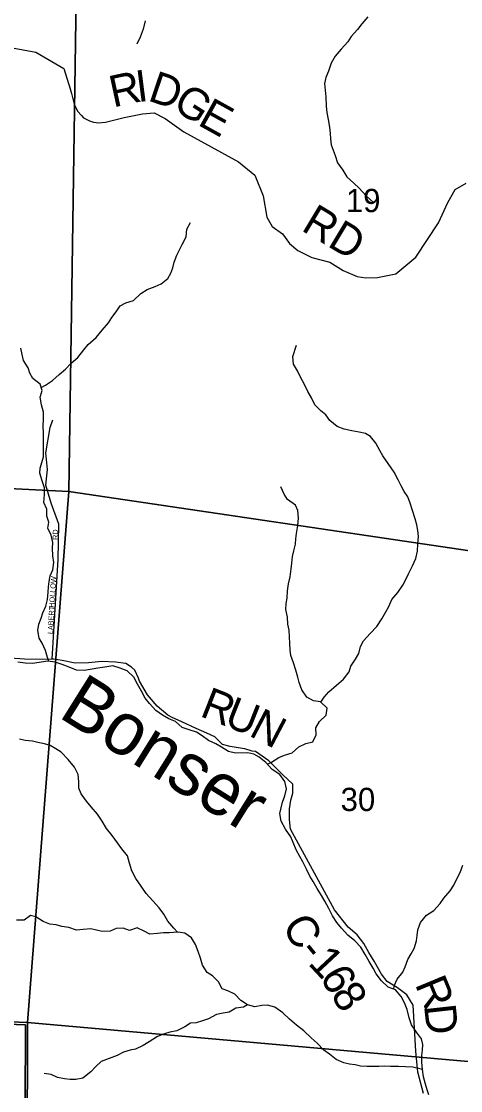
# Model space of a CAD drawing. Extents: x 1624196 to 2029251, y 146837 to 440034.
# Drawn here: x 1851645 to 1855817, y 286524 to 296690 of the extents above; entities that cross this region are included whole.
import ezdxf

# ---------------------------------------------------------------- set-up
doc = ezdxf.new("R2010")
doc.units = 0
for name, color, linetype in [('GM_X_County_Road', 7, 'Continuous'), ('GM_X_County_Road_Text', 7, 'Continuous'), ('GM_X_Minor_River', 7, 'Continuous'), ('GM_X_Minor_River_Text', 7, 'Continuous'), ('GM_X_Section', 7, 'Continuous'), ('GM_X_Section_Text', 7, 'Continuous'), ('GM_X_Township', 7, 'Continuous'), ('GM_X_Township_Subdivision', 7, 'Continuous'), ('GM_X_Township_Subdivision_Text', 7, 'Continuous')]:
    doc.layers.add(name, color=color, linetype=linetype)

msp = doc.modelspace()

# ---------------------------------------------------------------- linework, layer by layer
at = {"layer": 'GM_X_County_Road'}
for points in [[(1851418, 296464), (1851781, 296398), (1852048, 296243), (1852109, 296047), (1852120, 296004), (1852147, 295901), (1852176, 295837), (1852214, 295795), (1852233, 295772), (1852292, 295745), (1852331, 295732), (1852379, 295724), (1852445, 295730), (1852621, 295775), (1852795, 295812), (1852907, 295820), (1853011, 295765), (1853188, 295639), (1853706, 295355), (1853863, 295226), (1853940, 295032), (1853977, 294827), (1854027, 294739), (1854126, 294670), (1854190, 294578), (1854269, 294510), (1854403, 294444), (1854574, 294399), (1854700, 294322), (1854835, 294264), (1854915, 294252), (1855027, 294255), (1855201, 294290), (1855393, 294447), (1855607, 294773), (1855697, 294968), (1855764, 295091), (1855870, 295151)], [(1855465, 286496), (1855410, 286698), (1855391, 286898), (1855365, 287335), (1855305, 287435), (1855216, 287501), (1855120, 287561), (1855065, 287630), (1854995, 287754), (1854946, 287836), (1854896, 287922), (1854833, 288004), (1854749, 288078), (1854620, 288242), (1854202, 289009), (1854191, 289102), (1854191, 289202), (1854205, 289286), (1854222, 289352), (1854222, 289438), (1854125, 289528), (1853995, 289660), (1853868, 289747), (1853836, 289751), (1853766, 289773), (1853704, 289783), (1853629, 289796), (1853555, 289816), (1853481, 289888), (1853407, 289922), (1853306, 289967), (1853170, 290029), (1853077, 290070), (1853035, 290094), (1852935, 290178), (1852842, 290288), (1852767, 290416), (1852757, 290446), (1852723, 290520), (1852690, 290551), (1852636, 290585), (1852539, 290596), (1852410, 290604), (1852282, 290592), (1852154, 290589), (1852033, 290612), (1851950, 290627), (1851937, 290626), (1851847, 290622), (1851673, 290627), (1851537, 290636)]]:
    msp.add_lwpolyline(points, dxfattribs=at)
at = {"layer": 'GM_X_Minor_River'}
for points in [[(1854935, 296733), (1854879, 296666), (1854836, 296612), (1854776, 296546), (1854746, 296494), (1854682, 296426), (1854624, 296359), (1854586, 296293), (1854561, 296215), (1854537, 296157), (1854525, 296099), (1854529, 296037), (1854535, 295971), (1854541, 295884), (1854547, 295824), (1854558, 295756), (1854570, 295684), (1854578, 295624), (1854582, 295574), (1854586, 295516), (1854606, 295466), (1854624, 295416), (1854647, 295346), (1854697, 295276), (1854737, 295212), (1854803, 295150), (1854853, 295104), (1854921, 295032), (1854989, 294968)], [(1852820, 296694), (1852801, 296617), (1852773, 296541), (1852741, 296473)], [(1851833, 293210), (1851873, 293230), (1851940, 293274), (1852002, 293333), (1852064, 293383), (1852116, 293439), (1852180, 293493), (1852238, 293566), (1852280, 293618), (1852355, 293684), (1852411, 293754), (1852471, 293823), (1852505, 293875), (1852545, 293929), (1852583, 293985), (1852636, 294013), (1852710, 294035), (1852780, 294104), (1852838, 294140), (1852916, 294168), (1852972, 294194), (1853036, 294244), (1853064, 294295), (1853082, 294347), (1853097, 294399), (1853121, 294467), (1853173, 294567), (1853209, 294641), (1853217, 294714), (1853250, 294778)], [(1851906, 290605), (1851894, 290642), (1851872, 290709), (1851842, 290777), (1851814, 290827), (1851800, 290899), (1851810, 290959), (1851832, 291017), (1851849, 291067), (1851877, 291131), (1851891, 291193), (1851899, 291263), (1851903, 291313), (1851909, 291366), (1851919, 291418), (1851943, 291474), (1851952, 291544), (1851944, 291608), (1851940, 291680), (1851942, 291734), (1851926, 291804), (1851896, 291870), (1851904, 291930), (1851885, 291984), (1851885, 292053), (1851857, 292117), (1851863, 292191), (1851865, 292255), (1851841, 292321), (1851821, 292393), (1851824, 292443), (1851840, 292497), (1851854, 292549), (1851854, 292623), (1851856, 292691), (1851854, 292774), (1851852, 292842), (1851855, 292908), (1851855, 292974), (1851835, 293044), (1851823, 293116), (1851843, 293180), (1851823, 293242), (1851753, 293294), (1851724, 293344), (1851708, 293396), (1851666, 293466), (1851652, 293522), (1851638, 293584)], [(1854488, 290218), (1854520, 290266), (1854566, 290316), (1854638, 290379), (1854705, 290437), (1854759, 290507), (1854775, 290559), (1854819, 290625), (1854849, 290681), (1854867, 290746), (1854895, 290800), (1854958, 290870), (1855020, 290938), (1855068, 291008), (1855108, 291077), (1855134, 291127), (1855162, 291193), (1855221, 291261), (1855269, 291329), (1855297, 291382), (1855323, 291436), (1855359, 291512), (1855391, 291584), (1855406, 291654), (1855410, 291722), (1855416, 291792), (1855410, 291849), (1855400, 291903), (1855386, 291961), (1855360, 292041), (1855337, 292109), (1855317, 292169), (1855281, 292221), (1855253, 292275), (1855223, 292331), (1855185, 292405), (1855129, 292487), (1855079, 292559), (1855048, 292609), (1855012, 292681), (1854962, 292743), (1854912, 292771), (1854854, 292783), (1854784, 292796), (1854712, 292814), (1854644, 292838), (1854574, 292896), (1854538, 292948), (1854488, 292988), (1854432, 293044), (1854400, 293110), (1854364, 293170), (1854333, 293236), (1854297, 293306), (1854267, 293368), (1854229, 293432), (1854223, 293504), (1854259, 293612)], [(1853983, 289627), (1854020, 289648), (1854091, 289690), (1854145, 289714), (1854217, 289737), (1854281, 289791), (1854347, 289823), (1854413, 289839), (1854445, 289907), (1854443, 289973), (1854475, 290032), (1854540, 290094), (1854548, 290160), (1854486, 290220), (1854418, 290230), (1854356, 290264), (1854308, 290334), (1854284, 290404), (1854270, 290456), (1854252, 290522), (1854229, 290590), (1854205, 290660), (1854197, 290714), (1854195, 290774), (1854193, 290838), (1854187, 290902), (1854177, 290958), (1854174, 291024), (1854158, 291098), (1854160, 291155), (1854168, 291207), (1854174, 291275), (1854182, 291343), (1854198, 291409), (1854207, 291485), (1854213, 291539), (1854219, 291603), (1854233, 291655), (1854247, 291720), (1854251, 291770), (1854257, 291822), (1854272, 291896), (1854278, 291966), (1854270, 292038), (1854248, 292090), (1854174, 292144), (1854142, 292196), (1854108, 292266)], [(1854354, 288631), (1854318, 288699), (1854290, 288751), (1854255, 288813), (1854225, 288883), (1854203, 288937), (1854155, 289009), (1854111, 289085), (1854101, 289159), (1854111, 289212), (1854126, 289266), (1854148, 289328), (1854162, 289394), (1854148, 289462), (1854100, 289528), (1854028, 289578), (1853968, 289644), (1853904, 289694), (1853854, 289724), (1853796, 289734), (1853680, 289733), (1853612, 289749), (1853544, 289789), (1853493, 289821), (1853423, 289853), (1853361, 289897), (1853309, 289931), (1853239, 289953), (1853173, 289976), (1853109, 290032), (1853045, 290060), (1852985, 290094), (1852923, 290138), (1852861, 290204), (1852821, 290256), (1852787, 290322), (1852747, 290388), (1852714, 290456), (1852650, 290514), (1852584, 290540), (1852512, 290564), (1852438, 290550), (1852370, 290539), (1852316, 290531), (1852241, 290519), (1852169, 290523), (1852099, 290551), (1852031, 290575), (1851966, 290597), (1851895, 290606), (1851751, 290586), (1851679, 290588), (1851611, 290598)], [(1853128, 288029), (1853094, 288069), (1853036, 288135), (1852999, 288201), (1852953, 288261), (1852893, 288327), (1852829, 288399), (1852783, 288469), (1852733, 288541), (1852695, 288615), (1852672, 288687), (1852652, 288757), (1852598, 288823), (1852556, 288879), (1852508, 288951), (1852452, 289015), (1852412, 289087), (1852366, 289151), (1852307, 289223), (1852263, 289275), (1852211, 289345), (1852191, 289399), (1852189, 289461), (1852183, 289530), (1852149, 289598), (1852089, 289672), (1852022, 289741), (1851972, 289775), (1851918, 289805), (1851864, 289821), (1851802, 289833), (1851750, 289845), (1851680, 289853), (1851626, 289865)], [(1855516, 286483), (1855500, 286533), (1855484, 286585), (1855464, 286655), (1855456, 286725), (1855449, 286795), (1855449, 286859), (1855455, 286909), (1855457, 286961), (1855445, 287015), (1855397, 287079), (1855351, 287149), (1855328, 287217), (1855310, 287296), (1855284, 287360), (1855252, 287420), (1855198, 287482), (1855130, 287509), (1855064, 287569), (1855016, 287635), (1854986, 287687), (1854949, 287753), (1854911, 287817), (1854869, 287887), (1854811, 287947), (1854747, 288003), (1854685, 288069), (1854641, 288123), (1854601, 288187), (1854566, 288257), (1854526, 288325), (1854494, 288379), (1854454, 288445), (1854416, 288513), (1854386, 288563), (1854354, 288631)], [(1855181, 287488), (1855186, 287520), (1855214, 287584), (1855268, 287650), (1855291, 287702), (1855315, 287770), (1855347, 287824), (1855375, 287875), (1855399, 287947), (1855403, 287999), (1855409, 288053), (1855436, 288121), (1855494, 288191), (1855564, 288236), (1855624, 288304), (1855658, 288354), (1855718, 288424), (1855753, 288476), (1855779, 288530), (1855813, 288599), (1855837, 288669)], [(1855456, 286724), (1855430, 286731), (1855362, 286747), (1855292, 286751), (1855228, 286752), (1855152, 286752), (1855094, 286756), (1855040, 286752), (1854988, 286754), (1854928, 286754), (1854866, 286758), (1854814, 286768), (1854762, 286775), (1854706, 286789), (1854634, 286819), (1854572, 286871), (1854518, 286909), (1854453, 286975), (1854397, 287025), (1854329, 287091), (1854257, 287145), (1854191, 287203), (1854127, 287263), (1854051, 287319), (1853981, 287338), (1853929, 287334), (1853861, 287322), (1853791, 287340), (1853729, 287382), (1853671, 287442), (1853605, 287472), (1853553, 287492), (1853517, 287558), (1853459, 287616), (1853408, 287648), (1853366, 287718), (1853346, 287784), (1853324, 287848), (1853298, 287914), (1853260, 287978), (1853198, 288020), (1853130, 288030), (1853048, 288025), (1852996, 288023), (1852938, 288017), (1852866, 288011), (1852812, 288039), (1852744, 288071), (1852672, 288046), (1852612, 288070), (1852544, 288066), (1852488, 288040), (1852412, 288038), (1852304, 288062), (1852232, 288055), (1852168, 288049), (1852096, 288075), (1852028, 288083), (1851974, 288099), (1851916, 288107), (1851850, 288133), (1851782, 288177), (1851732, 288188), (1851670, 288144), (1851598, 288144)], [(1853791, 287340), (1853753, 287318), (1853681, 287308), (1853617, 287270), (1853561, 287261), (1853497, 287249), (1853423, 287207), (1853366, 287187), (1853306, 287169), (1853252, 287166), (1853196, 287132), (1853120, 287094), (1853056, 287080), (1853004, 287064), (1852936, 287040), (1852858, 286989), (1852800, 286953), (1852728, 286917), (1852677, 286909), (1852613, 286891), (1852555, 286858), (1852477, 286828), (1852403, 286800), (1852351, 286754), (1852303, 286704), (1852227, 286643), (1852161, 286631), (1852107, 286629), (1852055, 286635), (1851989, 286649), (1851927, 286677), (1851861, 286687)]]:
    msp.add_lwpolyline(points, dxfattribs=at)
at = {"layer": 'GM_X_Section'}
for points in [[(1852175, 297557), (1852094, 292219), (1846825, 292482), (1846824, 298136)], [(1857756, 297256), (1857402, 291435), (1852094, 292219), (1852175, 297557)], [(1846825, 292482), (1852094, 292219), (1851701, 287172), (1846426, 287370)], [(1852094, 292219), (1857402, 291435), (1857104, 286694), (1851701, 287172)], [(1851701, 287172), (1851691, 282090), (1846841, 282183), (1846426, 287370)], [(1857104, 286694), (1855877, 284540), (1855575, 282007), (1851691, 282090), (1851701, 287172)]]:
    msp.add_lwpolyline(points, close=True, dxfattribs=at)
at = {"layer": 'GM_X_Township'}
for points in [[(1851669, 283289), (1851683, 287150), (1846405, 287345)], [(1846405, 287345), (1851683, 287150), (1851669, 283289)]]:
    msp.add_lwpolyline(points, dxfattribs=at)
at = {"layer": 'GM_X_Township_Subdivision'}
msp.add_lwpolyline([(1851937, 290626), (1851993, 291574), (1851999, 291911), (1851926, 292109), (1851876, 292281), (1851893, 292430), (1851878, 292588), (1851917, 292827), (1851943, 292901)], dxfattribs=at)

# ---------------------------------------------------------------- texts
at = {"layer": 'GM_X_County_Road_Text'}
for s, rotation, p in [('I', 7.279, (1852750, 295921)), ('R', 12.2668, (1852516, 295870)), ('D', 341.3105, (1852836, 295940)), ('G', 327.3749, (1853069, 295864)), ('E', 330.9952, (1853309, 295711)), ('RD', 329.0369, (1854293, 294708)), ('R', 338.4965, (1853330, 290088)), ('U', 338.3055, (1853559, 289998)), ('N', 332.319, (1853796, 289904)), ('C', 301.4357, (1854113, 288089)), ('-', 309.2761, (1854267, 287842)), ('1', 313.0038, (1854359, 287731)), ('6', 299.7552, (1854474, 287610)), ('R', 292.5646, (1855380, 287537)), ('8', 303.0378, (1854576, 287434)), ('D', 276.2927, (1855469, 287331))]:
    msp.add_text(s, height=300, rotation=rotation, dxfattribs=at).set_placement(p)
at = {"layer": 'GM_X_Minor_River_Text'}
msp.add_text('Bonser', height=500, rotation=327.9985, dxfattribs=at).set_placement((1851983, 290083))
at = {"layer": 'GM_X_Section_Text'}
for s, p in [('19', (1854727, 294876)), ('30', (1854677, 289182))]:
    msp.add_text(s, height=221, rotation=0, dxfattribs=at).set_placement(p)
at = {"layer": 'GM_X_Township_Subdivision_Text'}
for s, rotation, p in [('RD', 90, (1851992, 291760)), ('HOLLOW', 86.1842, (1851957, 291114)), ('LABERT', 86.8217, (1851944, 290863))]:
    msp.add_text(s, height=50, rotation=rotation, dxfattribs=at).set_placement(p)

doc.saveas('drawing.dxf')
